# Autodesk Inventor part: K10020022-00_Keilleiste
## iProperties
Created: 2006-05
Part Number: K10020022-00_Keilleiste
Material: 1.0501 C35
Document SubType Name: Modeling
Designer: WKanehl
SBm.TeileNr: K10020022
SBm.TeileRev: 00
SBm.Rohteil: -
SBm.Werkstoff: C35
SBm.WerkstNr: 1.0501
SBm.Gewicht: 13,1
SBm.BenennD: Keilleiste - 112
SBm.BenennE: chock bank - 112
SBm.AenIndex1: 0.0
SBm.AenDatum1: 2006-03-31
SBm.AenName1: -
SBm.AenIndex2: 0.0
SBm.AenDatum2: 2006-03-31
SBm.AenName2: -
SBm.InvVersion: 10.0
Author: Hendriks
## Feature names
1. Extrusion1
2. Fase3 [Chamfer]
3. Bohrung3 [Hole]
4. Bohrung4 [Hole]
5. Bohrung5 [Hole]
